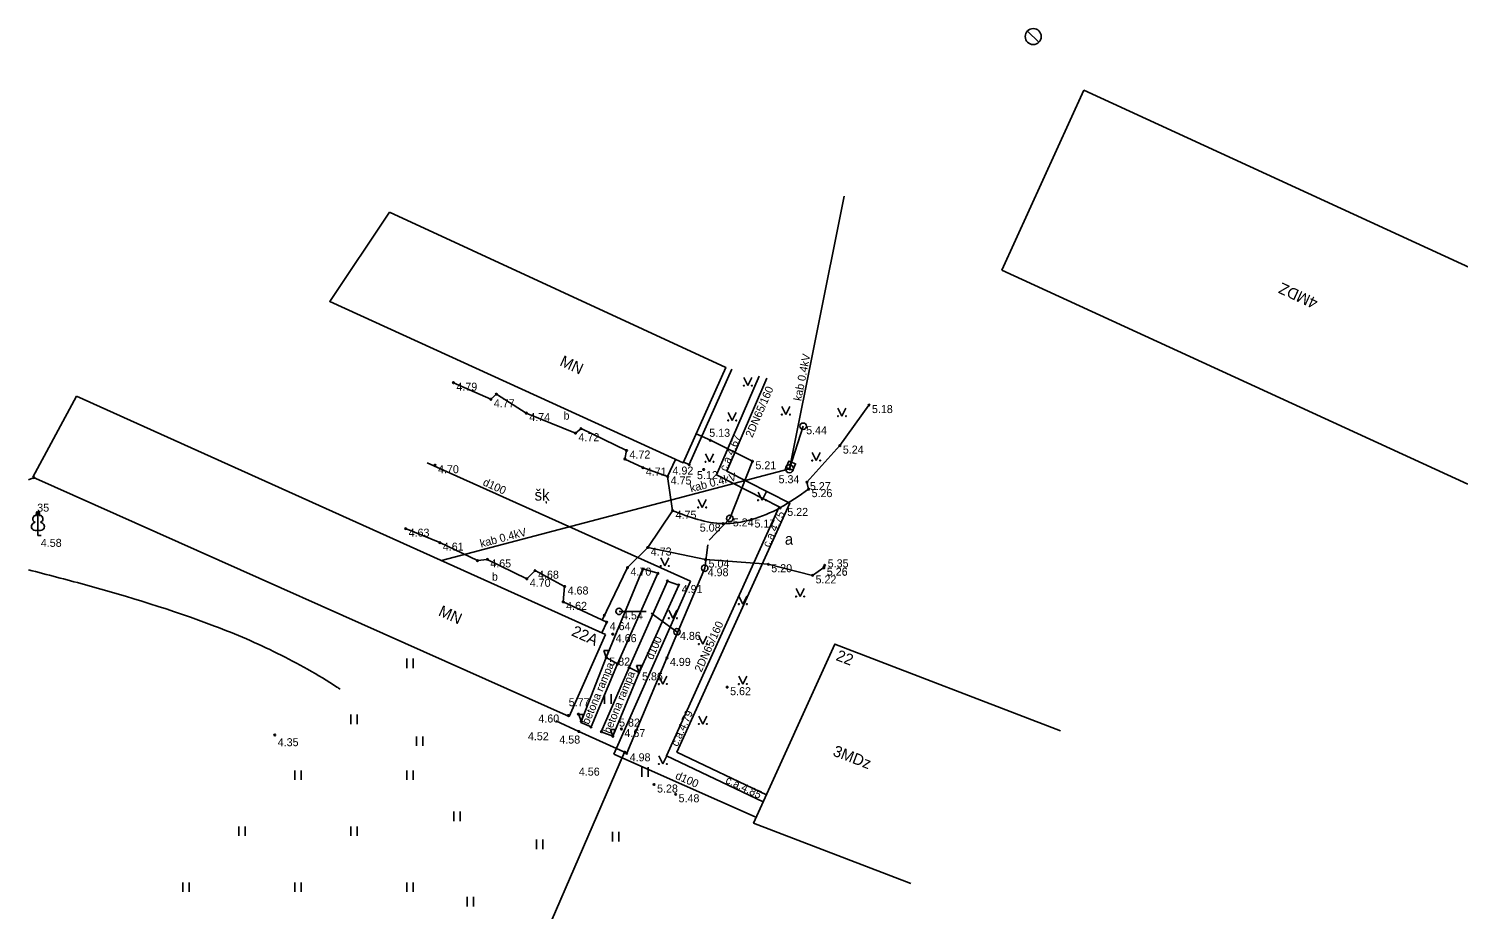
# Model space of a CAD drawing. Extents: x 484635 to 484808, y 278866 to 278977.
# Drawn here: x 484635.4 to 484724.7, y 278920.9 to 278976 of the extents above; entities that cross this region are included whole.
import ezdxf

# ---------------------------------------------------------------- set-up
doc = ezdxf.new("R2010")
doc.units = 0
for name, color, linetype in [('BUVE_BDET_####_####_#', 7, 'Continuous'), ('BUVE_BDET_####_TKST_#', 7, 'Continuous'), ('BUVE_EKAS_####_####_#', 7, 'Continuous'), ('BUVE_EKAS_ADRS_TKST_#', 7, 'Continuous'), ('BUVE_EKAS_RAKS_TKST_#', 7, 'Continuous'), ('CELI_CAPM_####_####_#', 7, 'Continuous'), ('CELI_CMAL_####_####_#', 7, 'Continuous'), ('CELI_CSEG_####_TKST_#', 7, 'Continuous'), ('CKOM_ELEM_####_####_#', 7, 'Continuous'), ('ELEK_ELEM_####_####_#', 7, 'Continuous'), ('ELEK_STUT_####_####_#', 7, 'Continuous'), ('ELEK_VADV_ZSPR_####_#', 7, 'Continuous'), ('ELEK_VADV_ZSPR_TKST_#', 7, 'Continuous'), ('NORB_ELEM_####_####_#', 7, 'Continuous'), ('NORB_ZOGS_BARJ_####_#', 7, 'Continuous'), ('NORB_ZOGS_ZSTP_####_#', 7, 'Continuous'), ('RELJ_AATZ_####_TKST_#', 7, 'Continuous'), ('RELJ_ELEM_####_####_#', 7, 'Continuous'), ('SILT_VADP_UDEN_####_#', 7, 'Continuous'), ('SILT_VADP_UDEN_TKST_#', 7, 'Continuous'), ('TERT_DIAM_####_TKST_#', 7, 'Continuous'), ('TERT_ELEM_####_####_#', 7, 'Continuous'), ('TERT_KONT_####_####_#', 7, 'Continuous'), ('UDTK_VADP_UDEN_####_#', 7, 'Continuous'), ('UDTK_VADP_UDEN_TKST_#', 7, 'Continuous')]:
    doc.layers.add(name, color=color, linetype=linetype)

msp = doc.modelspace()

# ---------------------------------------------------------------- linework, layer by layer
at = {"layer": 'BUVE_BDET_####_####_#'}
for p, q in [((484679.306, 278954.693), (484676.642, 278948.72)), ((484661.911, 278953.84), (484664.246, 278952.806)), ((484664.246, 278952.806), (484664.592, 278953.125)), ((484664.592, 278953.125), (484666.463, 278951.938)), ((484666.463, 278951.938), (484669.538, 278950.683)), ((484669.538, 278950.683), (484669.883, 278950.967)), ((484669.883, 278950.967), (484672.728, 278949.601)), ((484672.728, 278949.601), (484672.624, 278949.069)), ((484672.624, 278949.069), (484673.745, 278948.532)), ((484673.745, 278948.532), (484675.295, 278947.976)), ((484675.295, 278947.976), (484675.781, 278949.039)), ((484676.642, 278948.72), (484676.286, 278948.879)), ((484658.924, 278944.714), (484661.06, 278943.841)), ((484661.06, 278943.841), (484663.412, 278942.714)), ((484664.026, 278942.791), (484663.412, 278942.714)), ((484664.026, 278942.791), (484666.495, 278941.579)), ((484666.495, 278941.579), (484667.012, 278942.089)), ((484667.012, 278942.089), (484668.86, 278941.096)), ((484671.463, 278936.655), (484673.737, 278942.194)), ((484674.689, 278941.924), (484672.166, 278936.26)), ((484672.887, 278936.027), (484675.284, 278941.436)), ((484673.737, 278942.194), (484674.689, 278941.924)), ((484675.284, 278941.436), (484675.989, 278941.189)), ((484668.86, 278941.096), (484668.769, 278940.137)), ((484675.989, 278941.189), (484673.509, 278935.727)), ((484668.769, 278940.137), (484671.487, 278938.867)), ((484671.487, 278938.867), (484671.19, 278938.207)), ((484669.863, 278932.587), (484671.463, 278936.655)), ((484672.166, 278936.26), (484670.507, 278932.316)), ((484671.151, 278932.018), (484672.887, 278936.027)), ((484671.463, 278936.655), (484672.166, 278936.26)), ((484672.887, 278936.027), (484673.509, 278935.727)), ((484673.509, 278935.727), (484671.869, 278931.734)), ((484669.863, 278932.587), (484670.507, 278932.316)), ((484671.869, 278931.734), (484671.151, 278932.018))]:
    msp.add_line(p, q, dxfattribs=at)
at = {"layer": 'BUVE_EKAS_####_####_#'}
for p, q in [((484701.308, 278972.123), (484696.171, 278960.881)), ((484701.308, 278972.123), (484730.484, 278958.706)), ((484696.171, 278960.881), (484725.298, 278947.487)), ((484635.622, 278947.937), (484638.349, 278952.996)), ((484638.349, 278952.996), (484671.416, 278938.105)), ((484669.142, 278932.973), (484635.622, 278947.937)), ((484671.416, 278938.105), (484669.142, 278932.973))]:
    msp.add_line(p, q, dxfattribs=at)
msp.add_lwpolyline([(484657.913, 278964.513), (484678.924, 278954.793), (484676.26, 278948.82), (484654.181, 278958.911)], close=True, dxfattribs=at)
msp.add_lwpolyline([(484690.493, 278922.536), (484680.661, 278926.304), (484685.737, 278937.501), (484699.852, 278932.079)], dxfattribs=at)
at = {"layer": 'CELI_CAPM_####_####_#'}
msp.add_lwpolyline([(484684.105, 278947.185), (484684, 278947.622), (484686.058, 278949.908), (484687.877, 278952.442)], dxfattribs=at)
at = {"layer": 'CELI_CMAL_####_####_#'}
for p, q in [((484675.606, 278945.834), (484675.295, 278947.976)), ((484674.055, 278943.536), (484675.606, 278945.834))]:
    msp.add_line(p, q, dxfattribs=at)
for points in [[(484677.664, 278942.78), (484674.055, 278943.536), (484672.788, 278942.278), (484671.199, 278939.002)], [(484677.664, 278942.78), (484681.585, 278942.49), (484684.352, 278941.793), (484685.056, 278942.283)]]:
    msp.add_lwpolyline(points, dxfattribs=at)
msp.add_spline([(484675.606, 278945.834), (484678.769, 278945.029), (484680.536, 278945.286), (484682.312, 278946.012), (484684.105, 278947.185)], degree=3, dxfattribs=at)
at = {"layer": 'CKOM_ELEM_####_####_#'}
for p, q in [((484697.783, 278975.83), (484698.501, 278975.134)), ((484698.142, 278975.482), (484698.141, 278975.481))]:
    msp.add_line(p, q, dxfattribs=at)
msp.add_circle((484698.142, 278975.482), 0.5, dxfattribs=at)
at = {"layer": 'ELEK_ELEM_####_####_#'}
msp.add_lwpolyline([(484683.127, 278948.366), (484682.711, 278948.532), (484682.874, 278948.94), (484683.289, 278948.775)], close=True, dxfattribs=at)
for centre, radius in [((484683.766, 278951.118), 0.2), ((484682.907, 278948.463), 0.25)]:
    msp.add_circle(centre, radius, dxfattribs=at)
at = {"layer": 'ELEK_STUT_####_####_#'}
msp.add_line((484682.919, 278948.449), (484683.766, 278951.118), dxfattribs=at)
at = {"layer": 'ELEK_VADV_ZSPR_####_#'}
for p, q in [((484686.33, 278965.502), (484682.919, 278948.449)), ((484682.919, 278948.449), (484661.158, 278942.724))]:
    msp.add_line(p, q, dxfattribs=at)
at = {"layer": 'NORB_ELEM_####_####_#'}
for centre in [(484679.181, 278945.356), (484677.611, 278942.24), (484672.258, 278939.542), (484675.879, 278938.26)]:
    msp.add_circle(centre, 0.202, dxfattribs=at)
at = {"layer": 'NORB_ZOGS_BARJ_####_#'}
for p, q in [((484679.181, 278945.356), (484677.886, 278943.998)), ((484677.611, 278942.24), (484677.807, 278943.706)), ((484672.258, 278939.542), (484673.963, 278939.542)), ((484675.879, 278938.26), (484674.267, 278939.421))]:
    msp.add_line(p, q, dxfattribs=at)
at = {"layer": 'NORB_ZOGS_ZSTP_####_#'}
msp.add_line((484666.355, 278916.319), (484672.607, 278930.737), dxfattribs=at)
for points in [[(484677.966, 278950.24), (484677.071, 278950.639)], [(484679.181, 278945.356), (484680.595, 278948.927), (484677.966, 278950.24)], [(484635.361, 278947.766), (484635.702, 278947.903)], [(484669.746, 278932.033), (484672.738, 278930.669), (484675.251, 278936.635), (484677.611, 278942.24)], [(484669.746, 278932.033), (484668.311, 278932.695)]]:
    msp.add_lwpolyline(points, dxfattribs=at)
at = {"layer": 'RELJ_ELEM_####_####_#'}
for points in [[(484671.313, 278937.088), (484671.613, 278937.088), (484671.463, 278936.655)], [(484673.359, 278936.16), (484673.659, 278936.16), (484673.509, 278935.727)], [(484669.745, 278933.101), (484670.045, 278933.101), (484669.895, 278932.668)], [(484671.719, 278932.167), (484672.019, 278932.167), (484671.869, 278931.734)]]:
    msp.add_lwpolyline(points, close=True, dxfattribs=at)
for centre in [(484661.911, 278953.84), (484664.592, 278953.125), (484664.246, 278952.806), (484687.877, 278952.442), (484666.463, 278951.938), (484669.538, 278950.683), (484669.883, 278950.967), (484672.728, 278949.601), (484677.966, 278950.24), (484686.058, 278949.908), (484660.76, 278948.681), (484672.624, 278949.069), (484673.745, 278948.532), (484676.642, 278948.72), (484680.595, 278948.927), (484635.702, 278947.903), (484675.295, 278947.976), (484677.547, 278948.415), (484682.919, 278948.449), (484684, 278947.622), (484684.105, 278947.185), (484675.606, 278945.834), (484682.312, 278946.012), (484678.769, 278945.029), (484680.536, 278945.286), (484658.924, 278944.714), (484661.06, 278943.841), (484674.055, 278943.536), (484663.412, 278942.714), (484664.026, 278942.791), (484672.788, 278942.278), (484677.664, 278942.78), (484681.585, 278942.49), (484685.054, 278942.268), (484685.056, 278942.283), (484685.113, 278942.427), (484666.495, 278941.579), (484667.012, 278942.089), (484673.737, 278942.194), (484674.689, 278941.924), (484675.284, 278941.436), (484684.352, 278941.793), (484668.86, 278941.096), (484675.989, 278941.189), (484668.769, 278940.137), (484671.34, 278939.292), (484671.487, 278938.867), (484671.868, 278938.117), (484671.463, 278936.655), (484672.166, 278936.26), (484672.887, 278936.027), (484675.251, 278936.635), (484673.509, 278935.727), (484679.014, 278934.803), (484669.085, 278933.029), (484669.721, 278933.115), (484669.895, 278932.668), (484650.745, 278931.812), (484669.746, 278932.033), (484670.507, 278932.316), (484671.151, 278932.018), (484671.869, 278931.734), (484672.409, 278932.185), (484672.607, 278930.737), (484672.738, 278930.669), (484674.448, 278928.717), (484675.793, 278928.107)]:
    msp.add_circle(centre, 0.05, dxfattribs=at)
at = {"layer": 'SILT_VADP_UDEN_####_#'}
for points in [[(484681.005, 278954.247), (484678.354, 278948.075), (484682.275, 278946.088), (484675.214, 278930.508), (484681.26, 278927.625)], [(484681.466, 278928.08), (484675.872, 278930.748), (484682.928, 278946.318), (484678.998, 278948.309), (484681.494, 278954.118)]]:
    msp.add_lwpolyline(points, dxfattribs=at)
at = {"layer": 'TERT_ELEM_####_####_#'}
for p, q in [((484680.06, 278954.156), (484680.31, 278953.656)), ((484680.31, 278953.656), (484680.56, 278954.156)), ((484682.44, 278952.346), (484682.69, 278951.846)), ((484682.69, 278951.846), (484682.94, 278952.346)), ((484685.941, 278952.247), (484686.191, 278951.747)), ((484686.191, 278951.747), (484686.441, 278952.247)), ((484679.085, 278951.979), (484679.335, 278951.479)), ((484679.335, 278951.479), (484679.585, 278951.979)), ((484684.328, 278949.473), (484684.578, 278948.973)), ((484684.578, 278948.973), (484684.828, 278949.473)), ((484677.661, 278949.394), (484677.911, 278948.894)), ((484677.911, 278948.894), (484678.161, 278949.394)), ((484680.945, 278946.993), (484681.195, 278946.493)), ((484681.195, 278946.493), (484681.445, 278946.993)), ((484677.208, 278946.54), (484677.458, 278946.04)), ((484677.458, 278946.04), (484677.708, 278946.54)), ((484635.94, 278944.625), (484635.94, 278944.278)), ((484635.94, 278944.278), (484636.14, 278944.278)), ((484674.868, 278942.88), (484675.118, 278942.38)), ((484675.118, 278942.38), (484675.368, 278942.88)), ((484679.75, 278940.5), (484680, 278940)), ((484680, 278940), (484680.25, 278940.5)), ((484683.325, 278940.971), (484683.575, 278940.471)), ((484683.575, 278940.471), (484683.825, 278940.971)), ((484675.379, 278939.613), (484675.629, 278939.113)), ((484675.629, 278939.113), (484675.879, 278939.613)), ((484677.25, 278938), (484677.5, 278937.5)), ((484677.5, 278937.5), (484677.75, 278938)), ((484659, 278936), (484659, 278936.6)), ((484659.4, 278936), (484659.4, 278936.6)), ((484674.75, 278935.5), (484675, 278935)), ((484675, 278935), (484675.25, 278935.5)), ((484679.75, 278935.5), (484680, 278935)), ((484680, 278935), (484680.25, 278935.5)), ((484671.359, 278933.76), (484671.359, 278934.36)), ((484671.759, 278933.76), (484671.759, 278934.36)), ((484655.5, 278932.5), (484655.5, 278933.1)), ((484655.9, 278932.5), (484655.9, 278933.1)), ((484677.25, 278933), (484677.5, 278932.5)), ((484677.5, 278932.5), (484677.75, 278933)), ((484659.598, 278931.127), (484659.598, 278931.727)), ((484659.998, 278931.127), (484659.998, 278931.727)), ((484673.682, 278929.194), (484673.682, 278929.794)), ((484674.082, 278929.194), (484674.082, 278929.794)), ((484674.75, 278930.5), (484675, 278930)), ((484675, 278930), (484675.25, 278930.5)), ((484652, 278929), (484652, 278929.6)), ((484652.4, 278929), (484652.4, 278929.6)), ((484659, 278929), (484659, 278929.6)), ((484659.4, 278929), (484659.4, 278929.6)), ((484661.929, 278926.423), (484661.929, 278927.023)), ((484662.329, 278926.423), (484662.329, 278927.023)), ((484648.5, 278925.5), (484648.5, 278926.1)), ((484648.9, 278925.5), (484648.9, 278926.1)), ((484655.5, 278925.5), (484655.5, 278926.1)), ((484655.9, 278925.5), (484655.9, 278926.1)), ((484671.847, 278925.158), (484671.847, 278925.758)), ((484672.247, 278925.158), (484672.247, 278925.758)), ((484667.105, 278924.684), (484667.105, 278925.284)), ((484667.505, 278924.684), (484667.505, 278925.284)), ((484645, 278922), (484645, 278922.6)), ((484645.4, 278922), (484645.4, 278922.6)), ((484652, 278922), (484652, 278922.6)), ((484652.4, 278922), (484652.4, 278922.6)), ((484659, 278922), (484659, 278922.6)), ((484659.4, 278922), (484659.4, 278922.6)), ((484662.759, 278921.087), (484662.759, 278921.687)), ((484663.159, 278921.087), (484663.159, 278921.687))]:
    msp.add_line(p, q, dxfattribs=at)
for points in [[(484635.94, 278945.778), (484635.94, 278944.625)], [(484636.03, 278945.546), (484636.029, 278945.547)]]:
    msp.add_lwpolyline(points, dxfattribs=at)
for centre, radius in [((484680.059, 278953.655), 0.028), ((484680.559, 278953.655), 0.0263), ((484679.085, 278951.479), 0.028), ((484679.585, 278951.479), 0.0263), ((484682.44, 278951.845), 0.028), ((484682.94, 278951.845), 0.0263), ((484685.941, 278951.747), 0.028), ((484686.441, 278951.747), 0.0263), ((484677.661, 278948.893), 0.028), ((484678.161, 278948.893), 0.0263), ((484684.328, 278948.972), 0.028), ((484684.828, 278948.972), 0.0263), ((484677.208, 278946.04), 0.028), ((484677.708, 278946.04), 0.0263), ((484680.945, 278946.493), 0.028), ((484681.445, 278946.493), 0.0263), ((484674.868, 278942.379), 0.028), ((484675.368, 278942.379), 0.0263), ((484683.325, 278940.471), 0.028), ((484683.825, 278940.471), 0.0263), ((484679.75, 278940), 0.028), ((484680.25, 278940), 0.0263), ((484675.379, 278939.113), 0.028), ((484675.879, 278939.113), 0.0263), ((484677.25, 278937.5), 0.028), ((484677.75, 278937.5), 0.0263), ((484674.75, 278935), 0.028), ((484675.25, 278935), 0.0263), ((484679.75, 278935), 0.028), ((484680.25, 278935), 0.0263), ((484677.25, 278932.5), 0.028), ((484677.75, 278932.5), 0.0263), ((484674.75, 278930), 0.028), ((484675.25, 278930), 0.0263)]:
    msp.add_circle(centre, radius, dxfattribs=at)
for centre, major_axis, ratio, start_param, end_param in [((484635.85, 278944.871), (0.307, 0.095), 0.814445, 1.570796, 4.752015), ((484635.812, 278945.333), (-0.039, -0.212), 0.861323, 3.141593, 6.283185), ((484635.94, 278945.628), (0, -0.15), 0.707107, 3.14537, 5.287485), ((484635.94, 278945.628), (0, -0.15), 0.707107, 0.995701, 3.137816), ((484636.03, 278944.871), (-0.307, 0.095), 0.814445, 1.531171, 4.712389), ((484636.068, 278945.333), (0.039, -0.212), 0.861323, 0, 3.141593)]:
    msp.add_ellipse(centre, major_axis=major_axis, ratio=ratio, start_param=start_param, end_param=end_param, dxfattribs=at)
at = {"layer": 'TERT_KONT_####_####_#'}
msp.add_spline([(484654.827, 278934.683), (484654.629, 278934.813), (484650.908, 278936.918), (484648.968, 278937.82), (484646.98, 278938.622), (484638.85, 278941.221), (484635.361, 278942.138)], degree=3, dxfattribs=at)
at = {"layer": 'UDTK_VADP_UDEN_####_#'}
for p, q in [((484660.27, 278948.827), (484676.714, 278941.422)), ((484676.714, 278941.422), (484671.929, 278930.623)), ((484680.767, 278926.706), (484671.929, 278930.623))]:
    msp.add_line(p, q, dxfattribs=at)

# ---------------------------------------------------------------- texts
at = {"layer": 'BUVE_BDET_####_TKST_#'}
for p in [(484668.788, 278951.533), (484664.313, 278941.467)]:
    msp.add_text('b', height=0.5, dxfattribs=at).set_placement(p)
for rotation, p in [(67.18648, (484670.365, 278932.425)), (67.67112, (484671.709, 278931.861))]:
    msp.add_text('betona rampa', height=0.5, rotation=rotation, dxfattribs=at).set_placement(p)
at = {"layer": 'BUVE_EKAS_ADRS_TKST_#'}
for s, rotation, p in [('22A', 335.75662, (484669.234, 278938.055)), ('22', 338.98746, (484685.762, 278936.51)), ('3MDz', 338.98746, (484685.566, 278930.54))]:
    msp.add_text(s, height=0.7, rotation=rotation, dxfattribs=at).set_placement(p)
at = {"layer": 'BUVE_EKAS_RAKS_TKST_#'}
for s, rotation, p in [('4MDZ', 155.30475, (484715.998, 278959.058)), ('MN', 335.43767, (484668.499, 278954.94)), ('MN', 335.94306, (484660.916, 278939.308))]:
    msp.add_text(s, height=0.7, rotation=rotation, dxfattribs=at).set_placement(p)
at = {"layer": 'CELI_CSEG_####_TKST_#'}
for s, p in [('šķ', (484666.981, 278946.47)), ('a', (484682.617, 278943.71))]:
    msp.add_text(s, height=0.7, dxfattribs=at).set_placement(p)
at = {"layer": 'ELEK_VADV_ZSPR_TKST_#'}
for rotation, p in [(78.73846, (484683.641, 278952.669)), (14.73914, (484676.757, 278946.983)), (14.73914, (484663.638, 278943.532))]:
    msp.add_text('kab 0.4kV', height=0.5, rotation=rotation, dxfattribs=at).set_placement(p)
at = {"layer": 'RELJ_AATZ_####_TKST_#'}
for s, p in [(' 4.79', (484661.911, 278953.34)), (' 4.77', (484664.246, 278952.306)), (' 5.18', (484687.877, 278951.942)), (' 4.74', (484666.463, 278951.438)), (' 4.72', (484669.538, 278950.183)), (' 5.13', (484677.711, 278950.458)), (' 5.44', (484683.766, 278950.618)), (' 4.72', (484672.728, 278949.101)), (' 5.24', (484686.058, 278949.408)), (' 4.70', (484660.76, 278948.181)), (' 4.71', (484673.745, 278948.032)), (' 4.92', (484675.415, 278948.097)), (' 5.21', (484680.595, 278948.427)), (' 4.75', (484675.295, 278947.476)), (' 5.12', (484676.943, 278947.811)), (' 5.34', (484682.042, 278947.555)), (' 5.27', (484684, 278947.122)), (' 5.26', (484684.105, 278946.685)), (' 5.22', (484682.586, 278945.512)), (' 4.75', (484675.606, 278945.334)), (' 5.08', (484677.117, 278944.529)), (' 5.24', (484679.181, 278944.856)), (' 5.17', (484680.536, 278944.786)), (' 4.58', (484635.94, 278943.578)), (' 4.63', (484658.924, 278944.214)), (' 4.61', (484661.06, 278943.341)), (' 4.73', (484674.055, 278943.036)), (' 4.65', (484664.026, 278942.291)), (' 4.70', (484672.788, 278941.778)), (' 5.04', (484677.664, 278942.28)), (' 5.20', (484681.585, 278941.99)), (' 5.26', (484685.054, 278941.768)), (' 5.26', (484685.056, 278941.783)), (' 5.35', (484685.113, 278942.297)), (' 4.70', (484666.495, 278941.079)), (' 4.68', (484667.012, 278941.589)), (' 4.98', (484677.611, 278941.74)), (' 5.22', (484684.352, 278941.293)), (' 4.68', (484668.86, 278940.596)), (' 4.91', (484675.989, 278940.689)), (' 4.62', (484668.769, 278939.637)), (' 4.64', (484671.487, 278938.367)), (' 4.54', (484672.258, 278939.042)), (' 4.66', (484671.868, 278937.617)), (' 4.86', (484675.879, 278937.76)), (' 5.82', (484671.463, 278936.155)), (' 4.99', (484675.251, 278936.135)), (' 5.86', (484673.509, 278935.227)), (' 5.62', (484679.014, 278934.303)), (' 5.77', (484668.928, 278933.613)), (' 4.60', (484667.031, 278932.593)), (' 5.82', (484672.075, 278932.339)), (' 4.35', (484650.745, 278931.112)), (' 4.52', (484666.377, 278931.483)), (' 4.58', (484668.341, 278931.279)), (' 4.67', (484672.409, 278931.685)), (' 4.98', (484672.738, 278930.169)), (' 4.56', (484669.562, 278929.273)), (' 5.28', (484674.448, 278928.217)), (' 5.48', (484675.793, 278927.607))]:
    msp.add_text(s, height=0.5, dxfattribs=at).set_placement(p)
at = {"layer": 'SILT_VADP_UDEN_TKST_#'}
for s, rotation, p in [('2DN65/160', 66.75548, (484680.588, 278950.372)), ('c.a.4.67', 66.75548, (484678.96, 278948.269)), ('c.a.4.75', 65.62152, (484681.648, 278943.506)), ('2DN65/160', 65.62152, (484677.403, 278935.702)), ('c.a.4.79', 65.62152, (484675.918, 278931.051)), ('c.a.4.85', 334.50297, (484678.87, 278928.832))]:
    msp.add_text(s, height=0.5, rotation=rotation, dxfattribs=at).set_placement(p)
at = {"layer": 'TERT_DIAM_####_TKST_#'}
msp.add_text(' 35', height=0.5, dxfattribs=at).set_placement((484635.715, 278945.778))
at = {"layer": 'UDTK_VADP_UDEN_TKST_#'}
for rotation, p in [(335.75662, (484663.704, 278947.445)), (66.10177, (484674.361, 278936.481)), (336.10177, (484675.733, 278929.101))]:
    msp.add_text('d100', height=0.5, rotation=rotation, dxfattribs=at).set_placement(p)

doc.saveas('drawing.dxf')
